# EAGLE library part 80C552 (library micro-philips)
MICROCONTROLLER
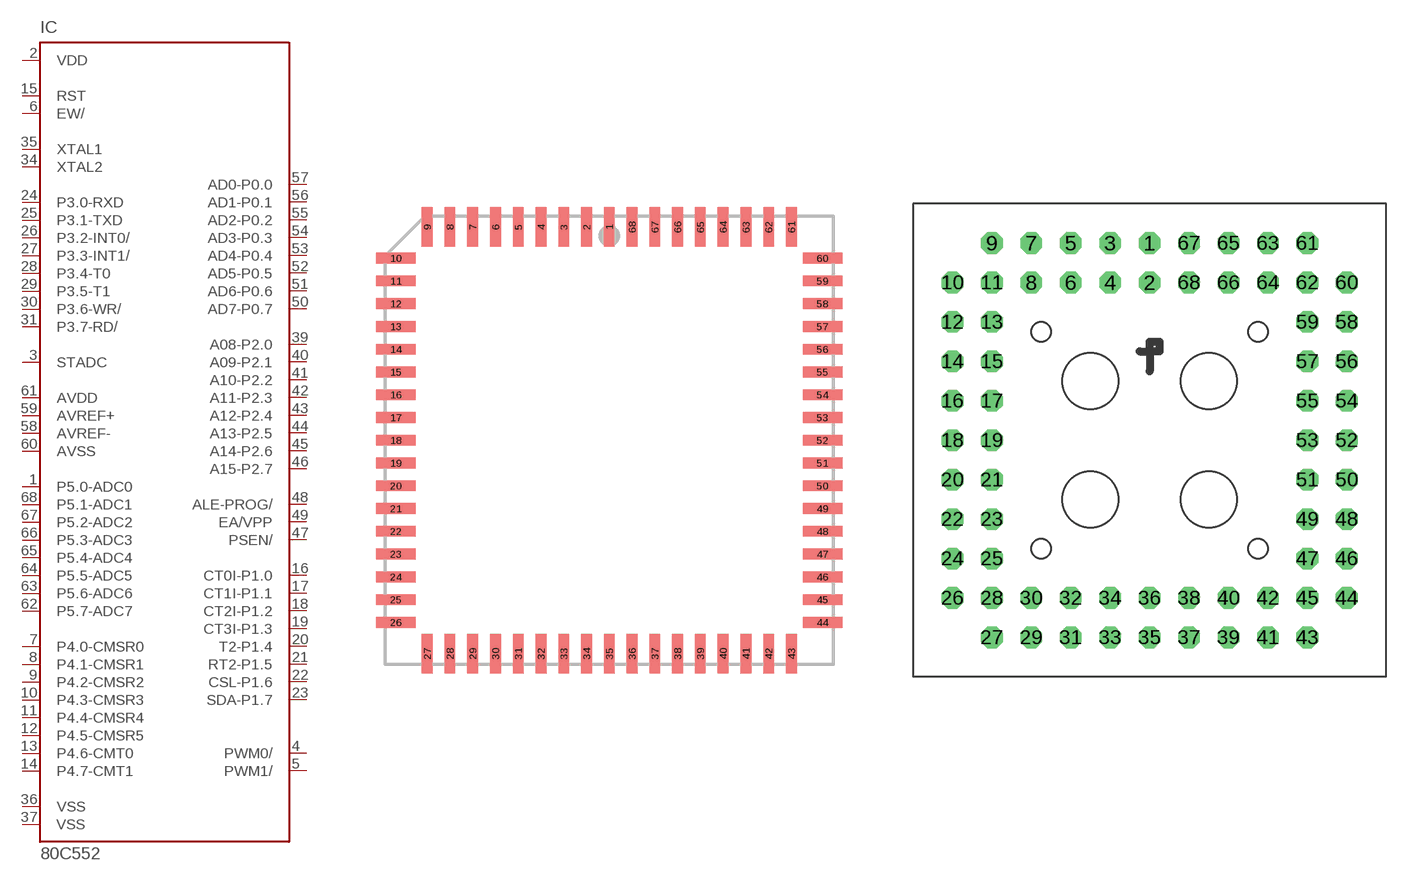
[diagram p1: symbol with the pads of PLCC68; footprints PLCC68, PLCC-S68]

Designator prefix IC

## 80C552 (MPN: P80C552IBA/08,512; OC_FARNELL: 1831232; OC_NEWARK: 70R8448)  [PLCC68]
1  P5.0-ADC0
2  VDD  pwr
3  STADC  in
4  PWM0/  out
5  PWM1/  out
6  EW/  in
7  P4.0-CMSR0
8  P4.1-CMSR1
9  P4.2-CMSR2
10  P4.3-CMSR3
11  P4.4-CMSR4
12  P4.5-CMSR5
13  P4.6-CMT0
14  P4.7-CMT1
15  RST
16  CT0I-P1.0
17  CT1I-P1.1
18  CT2I-P1.2
19  CT3I-P1.3
20  T2-P1.4
21  RT2-P1.5
22  CSL-P1.6
23  SDA-P1.7
24  P3.0-RXD
25  P3.1-TXD
26  P3.2-INT0/
27  P3.3-INT1/
28  P3.4-T0
29  P3.5-T1
30  P3.6-WR/
31  P3.7-RD/
32  NC1  nc
33  NC2  nc
34  XTAL2  out
35  XTAL1  in
36  VSS  pwr
37  VSS  pwr
38  NC3  nc
39  A08-P2.0
40  A09-P2.1
41  A10-P2.2
42  A11-P2.3
43  A12-P2.4
44  A13-P2.5
45  A14-P2.6
46  A15-P2.7
47  PSEN/  out
48  ALE-PROG/  out
49  EA/VPP  in
50  AD7-P0.7
51  AD6-P0.6
52  AD5-P0.5
53  AD4-P0.4
54  AD3-P0.3
55  AD2-P0.2
56  AD1-P0.1
57  AD0-P0.0
58  AVREF-  in
59  AVREF+  in
60  AVSS  in
61  AVDD  in
62  P5.7-ADC7
63  P5.6-ADC6
64  P5.5-ADC5
65  P5.4-ADC4
66  P5.3-ADC3
67  P5.2-ADC2
68  P5.1-ADC1

## 80C552N-S (MPN: P80C552IBA/08,512; OC_FARNELL: 1831233; OC_NEWARK: 70R8448)  [PLCC-S68]
Pads as for PLCC68

## Footprint PLCC68 (pad centres in mm)
PLASTIC LEADED CHIP CARRIER square
smd 0.6 x 2.2: 1 0,11.9; 2 -1.27,11.9; 3 -2.54,11.9; 4 -3.81,11.9; 5 -5.08,11.9; 6 -6.35,11.9; 7 -7.62,11.9; 8 -8.89,11.9; 9 -10.16,11.9; 27 -10.16,-11.9; 28 -8.89,-11.9; 29 -7.62,-11.9; 30 -6.35,-11.9; 31 -5.08,-11.9; 32 -3.81,-11.9; 33 -2.54,-11.9; 34 -1.27,-11.9; 35 0,-11.9; 36 1.27,-11.9; 37 2.54,-11.9; 38 3.81,-11.9; 39 5.08,-11.9; 40 6.35,-11.9; 41 7.62,-11.9; 42 8.89,-11.9; 43 10.16,-11.9; 61 10.16,11.9; 62 8.89,11.9; 63 7.62,11.9; 64 6.35,11.9; 65 5.08,11.9; 66 3.81,11.9; 67 2.54,11.9; 68 1.27,11.9
smd 2.2 x 0.6: 10 -11.9,10.16; 11 -11.9,8.89; 12 -11.9,7.62; 13 -11.9,6.35; 14 -11.9,5.08; 15 -11.9,3.81; 16 -11.9,2.54; 17 -11.9,1.27; 18 -11.9,0; 19 -11.9,-1.27; 20 -11.9,-2.54; 21 -11.9,-3.81; 22 -11.9,-5.08; 23 -11.9,-6.35; 24 -11.9,-7.62; 25 -11.9,-8.89; 26 -11.9,-10.16; 44 11.9,-10.16; 45 11.9,-8.89; 46 11.9,-7.62; 47 11.9,-6.35; 48 11.9,-5.08; 49 11.9,-3.81; 50 11.9,-2.54; 51 11.9,-1.27; 52 11.9,0; 53 11.9,1.27; 54 11.9,2.54; 55 11.9,3.81; 56 11.9,5.08; 57 11.9,6.35; 58 11.9,7.62; 59 11.9,8.89; 60 11.9,10.16

## Footprint PLCC-S68 (pad centres in mm)
PLASTIC LEADED CHIP CARRIER Socked
drill 0.813 pad 1.397 octagon: 1 0,12.7; 2 0,10.16; 3 -2.54,12.7; 4 -2.54,10.16; 5 -5.08,12.7; 6 -5.08,10.16; 7 -7.62,12.7; 8 -7.62,10.16; 9 -10.16,12.7; 10 -12.7,10.16; 11 -10.16,10.16; 12 -12.7,7.62; 13 -10.16,7.62; 14 -12.7,5.08; 15 -10.16,5.08; 16 -12.7,2.54; 17 -10.16,2.54; 18 -12.7,0; 19 -10.16,0; 20 -12.7,-2.54; 21 -10.16,-2.54; 22 -12.7,-5.08; 23 -10.16,-5.08; 24 -12.7,-7.62; 25 -10.16,-7.62; 26 -12.7,-10.16; 27 -10.16,-12.7; 28 -10.16,-10.16; 29 -7.62,-12.7; 30 -7.62,-10.16; 31 -5.08,-12.7; 32 -5.08,-10.16; 33 -2.54,-12.7; 34 -2.54,-10.16; 35 0,-12.7; 36 0,-10.16; 37 2.54,-12.7; 38 2.54,-10.16; 39 5.08,-12.7; 40 5.08,-10.16; 41 7.62,-12.7; 42 7.62,-10.16; 43 10.16,-12.7; 44 12.7,-10.16; 45 10.16,-10.16; 46 12.7,-7.62; 47 10.16,-7.62; 48 12.7,-5.08; 49 10.16,-5.08; 50 12.7,-2.54; 51 10.16,-2.54; 52 12.7,0; 53 10.16,0; 54 12.7,2.54; 55 10.16,2.54; 56 12.7,5.08; 57 10.16,5.08; 58 12.7,7.62; 59 10.16,7.62; 60 12.7,10.16; 61 10.16,12.7; 62 10.16,10.16; 63 7.62,12.7; 64 7.62,10.16; 65 5.08,12.7; 66 5.08,10.16; 67 2.54,12.7; 68 2.54,10.16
